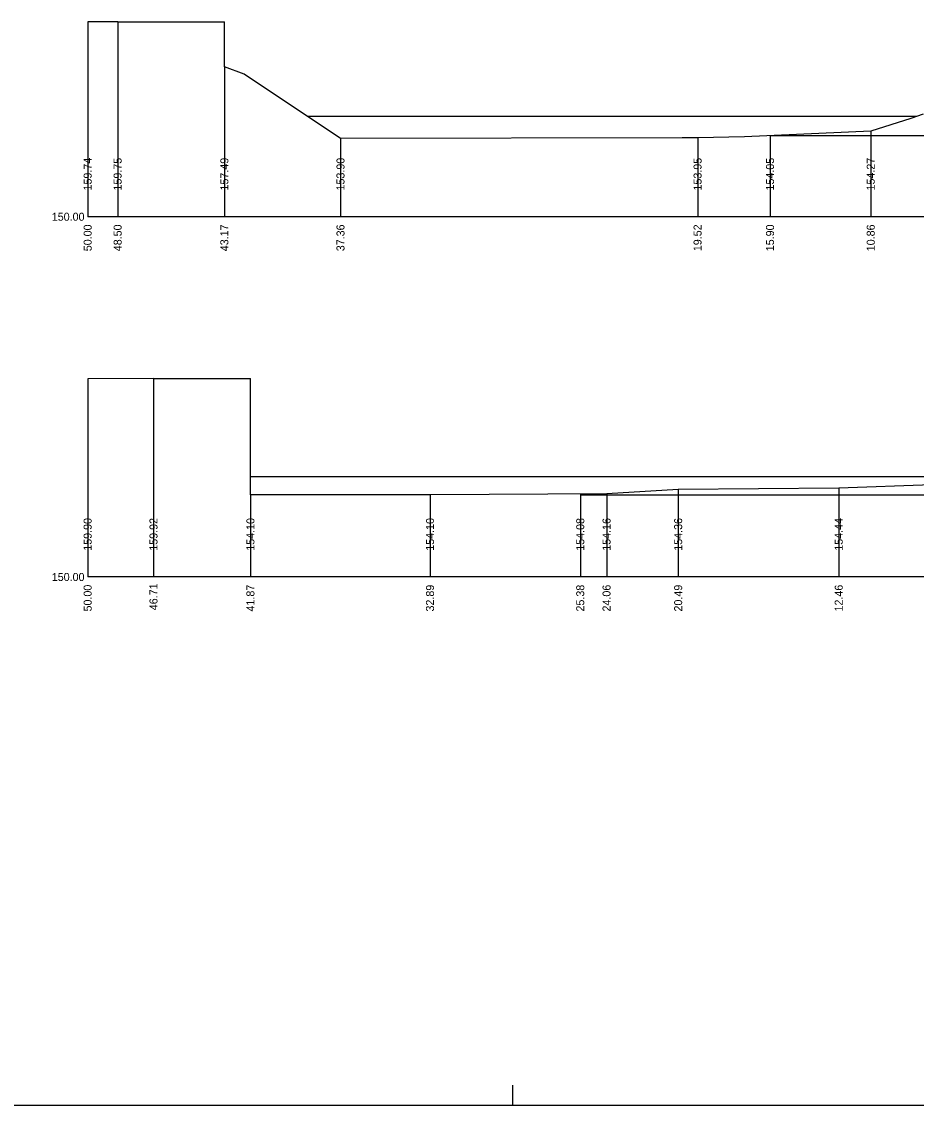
# Model space of a CAD drawing. Extents: x -582678 to -581845, y -1210354 to -1210235.
# Drawn here: x -582576 to -582531.3, y -1210354.1 to -1210299.9 of the extents above; entities that cross this region are included whole.
import ezdxf

# ---------------------------------------------------------------- set-up
doc = ezdxf.new("R2010")
doc.units = 0
for name, color, linetype in [('_N_popis', 7, 'Continuous'), ('_N_tučná', 7, 'Continuous'), ('_rámeček', 7, 'Continuous'), ('_S_hladina', 7, 'Continuous'), ('_S_popis', 7, 'Continuous'), ('_S_tenká', 7, 'Continuous'), ('_S_velmi_tenká', 7, 'Continuous')]:
    doc.layers.add(name, color=color, linetype=linetype)

msp = doc.modelspace()

# ---------------------------------------------------------------- linework, layer by layer
at = {"layer": '_N_popis'}
for points in [[(-582538.618, -1210305.641), (-582538.618, -1210309.691), (-582538.618, -1210309.691), (-582538.618, -1210309.691)], [(-582548.102, -1210323.535), (-582548.102, -1210327.691), (-582548.102, -1210327.691), (-582548.102, -1210327.691)]]:
    msp.add_lwpolyline(points, dxfattribs=at)
at = {"layer": '_N_tučná'}
for points in [[(-582483.319, -1210305.641), (-582538.618, -1210305.641)], [(-582477.814, -1210322.65), (-582477.814, -1210323.611), (-582548.102, -1210323.611)]]:
    msp.add_lwpolyline(points, dxfattribs=at)
at = {"layer": '_rámeček'}
for p, q in [((-582551.502, -1210353.091), (-582551.502, -1210354.091)), ((-582677.502, -1210354.091), (-582467.502, -1210354.091))]:
    msp.add_line(p, q, dxfattribs=at)
at = {"layer": '_S_hladina'}
msp.add_line((-582531.312, -1210304.691), (-582561.721, -1210304.691), dxfattribs=at)
msp.add_lwpolyline([(-582564.587, -1210322.671), (-582523.775, -1210322.671)], dxfattribs=at)
at = {"layer": '_S_tenká'}
for p, q in [((-582571.224, -1210299.945), (-582565.89, -1210299.945)), ((-582565.89, -1210302.2), (-582565.89, -1210299.945)), ((-582472.722, -1210309.691), (-582572.722, -1210309.691)), ((-582569.431, -1210317.771), (-582564.587, -1210317.771)), ((-582564.587, -1210323.589), (-582564.587, -1210317.771)), ((-582555.61, -1210323.589), (-582564.587, -1210323.589)), ((-582472.722, -1210327.691), (-582572.722, -1210327.691))]:
    msp.add_line(p, q, dxfattribs=at)
for points in [[(-582571.224, -1210299.945), (-582572.722, -1210299.949)], [(-582530.963, -1210304.566), (-582531.581, -1210304.787), (-582533.585, -1210305.421), (-582539.892, -1210305.697), (-582542.239, -1210305.742), (-582542.438, -1210305.743), (-582543.007, -1210305.747), (-582560.085, -1210305.787), (-582564.899, -1210302.561), (-582565.89, -1210302.2)], [(-582569.431, -1210317.771), (-582572.722, -1210317.791)], [(-582472.722, -1210318.274), (-582477.814, -1210318.274), (-582477.814, -1210322.65), (-582484.633, -1210322.652), (-582489.55, -1210322.914), (-582491.859, -1210322.999), (-582495.523, -1210323.057), (-582498.604, -1210323.229), (-582500.354, -1210323.401), (-582502.235, -1210323.421), (-582509.562, -1210323.456), (-582513.647, -1210323.167), (-582515.869, -1210323.022), (-582519.718, -1210322.525), (-582519.912, -1210322.505), (-582520.214, -1210322.516), (-582522.862, -1210322.541), (-582526.234, -1210323.021), (-582527.601, -1210323.112), (-582530.529, -1210323.094), (-582535.184, -1210323.254), (-582543.208, -1210323.328), (-582546.787, -1210323.535), (-582555.61, -1210323.589)]]:
    msp.add_lwpolyline(points, dxfattribs=at)
at = {"layer": '_S_velmi_tenká'}
for points in [[(-582572.722, -1210299.949), (-582572.722, -1210309.691), (-582572.722, -1210309.691), (-582572.722, -1210309.691)], [(-582571.224, -1210299.945), (-582571.224, -1210309.691), (-582571.224, -1210309.691), (-582571.224, -1210309.691)], [(-582565.89, -1210302.2), (-582565.89, -1210309.691), (-582565.89, -1210309.691), (-582565.89, -1210309.691)], [(-582533.585, -1210305.421), (-582533.585, -1210309.691), (-582533.585, -1210309.691), (-582533.585, -1210309.691)], [(-582560.085, -1210305.787), (-582560.085, -1210309.691), (-582560.085, -1210309.691), (-582560.085, -1210309.691)], [(-582542.239, -1210305.742), (-582542.239, -1210309.691), (-582542.239, -1210309.691), (-582542.239, -1210309.691)], [(-582572.722, -1210317.791), (-582572.722, -1210327.691), (-582572.722, -1210327.691), (-582572.722, -1210327.691)], [(-582569.431, -1210317.771), (-582569.431, -1210327.691), (-582569.431, -1210327.691), (-582569.431, -1210327.691)], [(-582543.208, -1210323.328), (-582543.208, -1210327.691), (-582543.208, -1210327.691), (-582543.208, -1210327.691)], [(-582535.184, -1210323.254), (-582535.184, -1210327.691), (-582535.184, -1210327.691), (-582535.184, -1210327.691)], [(-582564.587, -1210323.589), (-582564.587, -1210327.691), (-582564.587, -1210327.691), (-582564.587, -1210327.691)], [(-582555.61, -1210323.589), (-582555.61, -1210327.691), (-582555.61, -1210327.691), (-582555.61, -1210327.691)], [(-582546.787, -1210323.535), (-582546.787, -1210327.691), (-582546.787, -1210327.691), (-582546.787, -1210327.691)]]:
    msp.add_lwpolyline(points, dxfattribs=at)

# ---------------------------------------------------------------- texts
at = {"layer": '_N_popis'}
for s, p in [('154.05', (-582538.425, -1210308.382)), ('15.90', (-582538.425, -1210311.415)), ('154.08', (-582547.909, -1210326.382)), ('25.38', (-582547.909, -1210329.417))]:
    msp.add_text(s, height=0.4, rotation=90, dxfattribs=at).set_placement(p)
at = {"layer": '_S_popis'}
for s, p in [('159.74', (-582572.529, -1210308.381)), ('159.75', (-582571.031, -1210308.382)), ('157.49', (-582565.697, -1210308.382)), ('153.90', (-582559.892, -1210308.381)), ('153.95', (-582542.046, -1210308.382)), ('154.27', (-582533.392, -1210308.381)), ('50.00', (-582572.529, -1210311.415)), ('48.50', (-582571.031, -1210311.415)), ('43.17', (-582565.697, -1210311.416)), ('37.36', (-582559.892, -1210311.416)), ('19.52', (-582542.046, -1210311.413)), ('10.86', (-582533.392, -1210311.416)), ('159.90', (-582572.529, -1210326.381)), ('159.92', (-582569.238, -1210326.38)), ('154.10', (-582564.394, -1210326.381)), ('154.10', (-582555.417, -1210326.381)), ('154.16', (-582546.594, -1210326.381)), ('154.36', (-582543.015, -1210326.381)), ('154.44', (-582534.991, -1210326.381)), ('50.00', (-582572.529, -1210329.415)), ('46.71', (-582569.238, -1210329.353)), ('41.87', (-582564.394, -1210329.416)), ('32.89', (-582555.417, -1210329.417)), ('24.06', (-582546.594, -1210329.416)), ('20.49', (-582543.015, -1210329.417)), ('12.46', (-582534.991, -1210329.416))]:
    msp.add_text(s, height=0.4, rotation=90, dxfattribs=at).set_placement(p)
for p in [(-582574.521, -1210309.891), (-582574.521, -1210327.891)]:
    msp.add_text('150.00', height=0.4, dxfattribs=at).set_placement(p)

doc.saveas('drawing.dxf')
